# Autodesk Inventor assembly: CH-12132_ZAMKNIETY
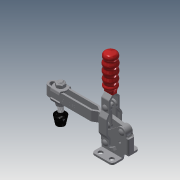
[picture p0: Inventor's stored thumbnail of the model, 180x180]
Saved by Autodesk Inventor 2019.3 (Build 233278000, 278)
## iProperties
Company: Î¢ÈíÖÐ¹ú
Created: 2012-09
Part Number: CH-12132_ZAMKNIETY
Material: Ogólny
Description: STEP AP203
Document SubType Name: Assembly
Designer: CADENGINEERING4
Sending System: SolidWorks 2010
Preprocessor: SwSTEP 2.0
Title: CH-12132.STEP
Author: Î¢ÈíÓÃ»§
Revision Number: ÈÎºÎ
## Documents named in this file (12)
- D:\Vault_2016\Projekty\STRONA\Vertical toggle clamp\Do zrobienia 3\CH-12132\CH-12132_ZAMKNIETY.iam
- D:\Vault_2016\Projekty\STRONA\Vertical toggle clamp\Do zrobienia 3\CH-12132\CH-12130-08.ipt
- D:\Vault_2016\Projekty\STRONA\Vertical toggle clamp\Do zrobienia 3\CH-12132\CH-12130-07.ipt
- D:\Vault_2016\Projekty\STRONA\Vertical toggle clamp\Do zrobienia 3\CH-12132\CH-12130-06.ipt
- D:\Vault_2016\Projekty\STRONA\Vertical toggle clamp\Do zrobienia 3\CH-12132\CH-FW-516.ipt
- D:\Vault_2016\Projekty\STRONA\Vertical toggle clamp\Do zrobienia 3\CH-12132\CH-12130-04 CONNECTING-PLATE.ipt
- D:\Vault_2016\Projekty\STRONA\Vertical toggle clamp\Do zrobienia 3\CH-12132\CH-12130-01 FLANGED BASE.ipt
- D:\Vault_2016\Projekty\STRONA\Vertical toggle clamp\Do zrobienia 3\CH-12132\CH-12130-05.ipt
- D:\Vault_2016\Projekty\STRONA\Vertical toggle clamp\Do zrobienia 3\CH-12132\CH-FC-56212 SPINDLE SUPPLIED.ipt
- D:\Vault_2016\Projekty\STRONA\Vertical toggle clamp\Do zrobienia 3\CH-12132\CH-12130-03 STRAIGHT HANDLE.ipt
- D:\Vault_2016\Projekty\STRONA\Vertical toggle clamp\Do zrobienia 3\CH-12132\CH-FC-56212 Nut.ipt
- D:\Vault_2016\Projekty\STRONA\Vertical toggle clamp\Do zrobienia 3\CH-12132\CH-12132-02 LONG U-BAR.ipt
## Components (15 placed, 15 different names)
1. CH-12130-08_1
2. CH-12130-07_2
3. CH-12130-06_3
4. CH-FW-516_4
5. CH-12130-08_5
6. CH-12130-04 CONNECTING-PLATE_6
7. CH-12130-01 FLANGED BASE_7
8. CH-12130-06_8
9. CH-12130-05_9
10. CH-FW-516_10
11. CH-FC-56212 SPINDLE SUPPLIED_11
12. CH-12130-03 STRAIGHT HANDLE_12
13. CH-FC-56212 Nut_13
14. CH-FC-56212 Nut_14
15. CH-12132-02 LONG U-BAR_15
